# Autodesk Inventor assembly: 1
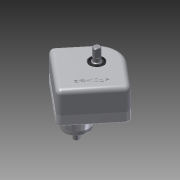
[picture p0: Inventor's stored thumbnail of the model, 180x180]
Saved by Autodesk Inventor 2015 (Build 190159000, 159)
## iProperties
Created: 2015-11
Part Number: 1
Document SubType Name: Assembly
Designer: 702
Author: 702
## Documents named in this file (13)
- E:\Inventor2급-박문수\공용부품_20151104_2\1.iam
- E:\Inventor2급-박문수\공용부품_20151104_2\본체.ipt
- E:\Inventor2급-박문수\공용부품_20151104_2\베어링 6002.ipt
- E:\Inventor2급-박문수\공용부품_20151104_2\로드 축.ipt
- E:\Inventor2급-박문수\공용부품_20151104_2\앞커버.ipt
- E:\Inventor2급-박문수\공용부품_20151104_2\오일실 15 x 25.ipt
- E:\Inventor2급-박문수\공용부품_20151104_2\베어링 6001.ipt
- E:\Inventor2급-박문수\공용부품_20151104_2\축 커버.ipt
- E:\Inventor2급-박문수\공용부품_20151104_2\M3 x 0.5.ipt
- E:\Inventor2급-박문수\공용부품_20151104_2\오일실 12 x 22.ipt
- E:\Inventor2급-박문수\공용부품_20151104_2\편심 축.ipt
- E:\Inventor2급-박문수\공용부품_20151104_2\로드.ipt
- E:\Inventor2급-박문수\공용부품_20151104_2\M4 x 0.7.ipt
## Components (9 placed, 2 different names)
1. M4 x 0.7:1 — 각도:1
2. M4 x 0.7:2 — 각도:3
3. M4 x 0.7:3 — 각도:4
4. M4 x 0.7:4 — 각도:6
5. M4 x 0.7:5 — 각도:5
6. M3 x 0.5:1 — 각도:2
7. M3 x 0.5:2
8. M3 x 0.5:3
9. M3 x 0.5:4
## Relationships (6: Angle 6)
- 각도:1 [Angle]: M4 x 0.7:1
- 각도:2 [Angle]: M3 x 0.5:1
- 각도:3 [Angle]: M4 x 0.7:2
- 각도:4 [Angle]: M4 x 0.7:3
- 각도:5 [Angle]: M4 x 0.7:5
- 각도:6 [Angle]: M4 x 0.7:4
